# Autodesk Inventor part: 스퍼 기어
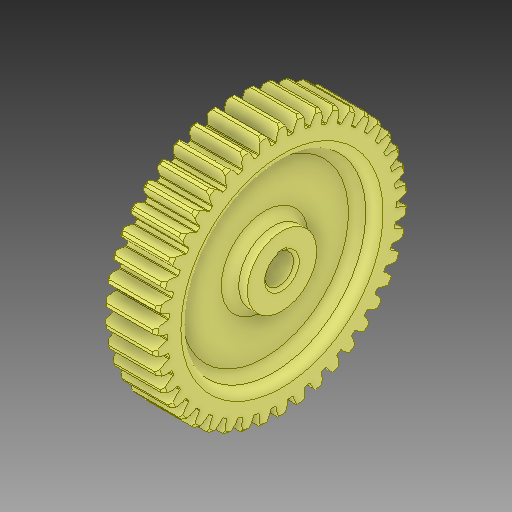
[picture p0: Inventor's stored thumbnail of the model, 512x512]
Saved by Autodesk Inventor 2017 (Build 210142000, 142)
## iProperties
Created: 2024-09
Part Number: 스퍼 기어
Material: 일반
Document SubType Name: Modeling
Designer: MRC
Density: 1 g/cm^3
Appearance: 기본값
Author: jhkim
Sending System: Autodesk Inventor 2025
Preprocessor: ST-DEVELOPER v20
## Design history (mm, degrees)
feature "솔리드1"
node "솔리드2"
